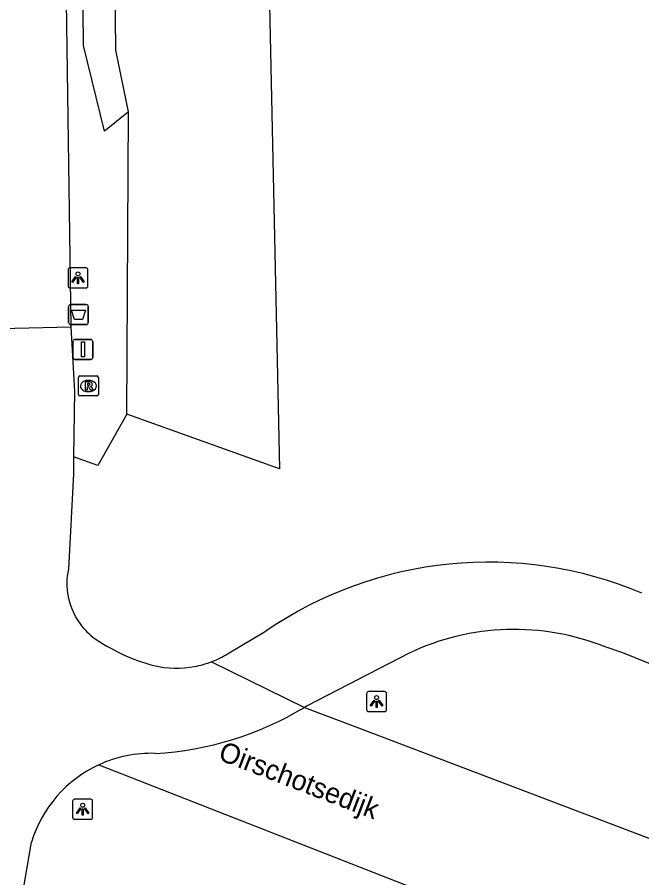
# Model space of a CAD drawing. Extents: x 155209 to 156823, y 385356 to 388482.
# Drawn here: x 155383.98 to 155415.19, y 386855.08 to 386898.09 of the extents above; entities that cross this region are included whole.
import ezdxf

# ---------------------------------------------------------------- set-up
doc = ezdxf.new("R2010")
doc.units = 0
for name, color, linetype in [('IMGEO_Afvalbak', 7, 'Continuous'), ('IMGEO_Fietspad_gesloten', 7, 'Continuous'), ('IMGEO_Groenvoorziening', 7, 'Continuous'), ('IMGEO_Lichtpunt', 7, 'Continuous'), ('IMGEO_Openbare_ruimte_label', 7, 'Continuous'), ('IMGEO_Rijbaan_lokaal_gesloten', 7, 'Continuous'), ('IMGEO_Rioolput', 7, 'Continuous'), ('IMGEO_Verkeersbordpaal', 7, 'Continuous'), ('IMGEO_Waterloop', 7, 'Continuous')]:
    doc.layers.add(name, color=color, linetype=linetype)

msp = doc.modelspace()

# ---------------------------------------------------------------- linework, layer by layer
at = {"layer": 'IMGEO_Afvalbak'}
for p, q in [((155386.544, 386882.829), (155386.544, 386883.629)), ((155386.544, 386883.629), (155386.544, 386882.829)), ((155386.644, 386883.729), (155387.434, 386883.729)), ((155387.434, 386883.729), (155386.644, 386883.729)), ((155387.534, 386883.629), (155387.534, 386882.829)), ((155387.534, 386882.829), (155387.534, 386883.629)), ((155387.434, 386882.729), (155386.644, 386882.729)), ((155386.644, 386882.729), (155387.434, 386882.729))]:
    msp.add_line(p, q, dxfattribs=at)
msp.add_lwpolyline([(155386.687, 386883.443), (155387.391, 386883.443), (155387.242, 386882.973), (155386.836, 386882.973), (155386.687, 386883.443)], dxfattribs=at)
for centre, start, end in [((155386.644, 386883.629), 90, 180), ((155386.644, 386883.629), 90, 180), ((155387.434, 386883.629), 0, 90), ((155387.434, 386883.629), 360, 90), ((155386.644, 386882.829), 180, 270), ((155386.644, 386882.829), 180, 270), ((155387.434, 386882.829), 270, 0), ((155387.434, 386882.829), 270, 0)]:
    msp.add_arc(centre, 0.1, start, end, dxfattribs=at)
at = {"layer": 'IMGEO_Fietspad_gesloten'}
for points in [[(155385.413, 386956.748), (155385.603, 386955.738), (155386.663, 386882.616)], [(155383.155, 386882.53), (155386.663, 386882.616)], [(155386.663, 386882.616), (155386.843, 386879.394), (155386.801, 386876.114)], [(155386.801, 386876.114), (155386.79, 386875.274), (155386.535, 386870.503)], [(155394.487, 386866.267), (155396.425, 386867.426)], [(155466.767, 386846.51), (155418.719, 386864.507), (155414.232, 386866.333), (155413.361, 386866.621)], [(155403.572, 386866.316), (155398.462, 386863.678), (155398.335, 386863.601)], [(155393.692, 386865.88), (155398.335, 386863.601)], [(155376.591, 386809.635), (155377.495, 386814.325), (155383.299, 386848.707), (155384.694, 386856.865)]]:
    msp.add_lwpolyline(points, dxfattribs=at)
for centre, radius, start, end in [((155389.897, 386869.798), 3.435, 168.1555, 213.8152), ((155407.522, 386851.188), 19.668, 67.0661, 124.3484), ((155389.896, 386869.791), 3.43, 213.7329, 231.3216), ((155408.816, 386855.242), 12.253, 68.2278, 115.3414), ((155393.271, 386874.947), 9.583, 234.8348, 255.1048), ((155391.895, 386870.581), 5.033, 290.917, 300.996), ((155391.901, 386870.624), 5.071, 280.6868, 290.6876), ((155391.932, 386870.508), 4.951, 256.8808, 280.5831), ((155390.673, 386855.055), 6.247, 114.7756, 163.16)]:
    msp.add_arc(centre, radius, start, end, dxfattribs=at)
at = {"layer": 'IMGEO_Groenvoorziening'}
for points in [[(155395.168, 386964.319), (155397.089, 386875.516), (155389.459, 386878.251)], [(155389.459, 386878.251), (155389.537, 386893.35)], [(155389.459, 386878.251), (155388.004, 386875.687), (155386.801, 386876.114)]]:
    msp.add_lwpolyline(points, dxfattribs=at)
at = {"layer": 'IMGEO_Lichtpunt'}
for p, q in [((155387.422, 386885.558), (155386.614, 386885.558)), ((155387.422, 386885.558), (155386.614, 386885.558)), ((155386.52, 386885.463), (155386.52, 386884.656)), ((155386.52, 386885.463), (155386.52, 386884.656)), ((155387.516, 386884.656), (155387.516, 386885.463)), ((155387.516, 386884.656), (155387.516, 386885.463)), ((155386.614, 386884.562), (155387.422, 386884.562)), ((155386.614, 386884.562), (155387.422, 386884.562)), ((155401.436, 386864.292), (155401.436, 386863.485)), ((155401.436, 386864.292), (155401.436, 386863.485)), ((155402.338, 386864.387), (155401.53, 386864.387)), ((155402.338, 386864.387), (155401.53, 386864.387)), ((155402.432, 386863.485), (155402.432, 386864.292)), ((155402.432, 386863.485), (155402.432, 386864.292)), ((155401.53, 386863.391), (155402.338, 386863.391)), ((155401.53, 386863.391), (155402.338, 386863.391)), ((155386.749, 386858.912), (155386.749, 386858.105)), ((155386.749, 386858.912), (155386.749, 386858.105)), ((155387.651, 386859.007), (155386.843, 386859.007)), ((155387.651, 386859.007), (155386.843, 386859.007)), ((155387.745, 386858.105), (155387.745, 386858.912)), ((155387.745, 386858.105), (155387.745, 386858.912)), ((155386.843, 386858.011), (155387.651, 386858.011)), ((155386.843, 386858.011), (155387.651, 386858.011))]:
    msp.add_line(p, q, dxfattribs=at)
for points in [[(155386.894, 386885.127), (155386.933, 386885.099), (155386.745, 386884.837), (155386.707, 386884.864), (155386.894, 386885.127)], [(155386.996, 386885.079), (155387.043, 386885.079), (155387.043, 386884.757), (155386.996, 386884.757), (155386.996, 386885.079)], [(155387.106, 386885.099), (155387.144, 386885.126), (155387.331, 386884.864), (155387.292, 386884.836), (155387.106, 386885.099)], [(155401.81, 386863.956), (155401.849, 386863.928), (155401.661, 386863.666), (155401.623, 386863.693), (155401.81, 386863.956)], [(155401.912, 386863.908), (155401.959, 386863.908), (155401.959, 386863.586), (155401.912, 386863.586), (155401.912, 386863.908)], [(155402.022, 386863.928), (155402.06, 386863.955), (155402.247, 386863.693), (155402.208, 386863.665), (155402.022, 386863.928)], [(155387.123, 386858.576), (155387.162, 386858.548), (155386.974, 386858.286), (155386.936, 386858.313), (155387.123, 386858.576)], [(155387.225, 386858.528), (155387.272, 386858.528), (155387.272, 386858.206), (155387.225, 386858.206), (155387.225, 386858.528)], [(155387.335, 386858.548), (155387.373, 386858.575), (155387.56, 386858.313), (155387.521, 386858.285), (155387.335, 386858.548)]]:
    msp.add_lwpolyline(points, dxfattribs=at)
for centre in [(155387.019, 386885.261), (155401.935, 386864.09), (155387.248, 386858.71)]:
    msp.add_circle(centre, 0.0994, dxfattribs=at)
for centre, start, end in [((155386.614, 386885.463), 90, 180), ((155386.614, 386885.463), 90, 180), ((155387.422, 386885.463), 0, 90), ((155387.422, 386885.463), 0, 90), ((155386.614, 386884.656), 180, 270), ((155386.614, 386884.656), 180, 270), ((155387.422, 386884.656), 270, 0), ((155387.422, 386884.656), 270, 360), ((155401.53, 386864.292), 90, 180), ((155401.53, 386864.292), 90, 180), ((155402.338, 386864.292), 0, 90), ((155402.338, 386864.292), 0, 90), ((155401.53, 386863.485), 180, 270), ((155401.53, 386863.485), 180, 270), ((155402.338, 386863.485), 270, 0), ((155402.338, 386863.485), 270, 360), ((155386.843, 386858.912), 90, 180), ((155386.843, 386858.912), 90, 180), ((155387.651, 386858.912), 0, 90), ((155387.651, 386858.912), 0, 90), ((155386.843, 386858.105), 180, 270), ((155386.843, 386858.105), 180, 270), ((155387.651, 386858.105), 270, 0), ((155387.651, 386858.105), 270, 360)]:
    msp.add_arc(centre, 0.0946, start, end, dxfattribs=at)
at = {"layer": 'IMGEO_Rijbaan_lokaal_gesloten'}
for points in [[(155398.335, 386863.601), (155400.892, 386862.631), (155414.712, 386857.387), (155445.113, 386845.774), (155457.912, 386840.913)], [(155388.055, 386860.727), (155422.593, 386847.21), (155447.01, 386837.973), (155453.658, 386835.338), (155457.34, 386833.958)]]:
    msp.add_lwpolyline(points, dxfattribs=at)
for centre, radius, start, end in [((155389.954, 386877.519), 16.247, 273.2741, 301.0545), ((155390.677, 386855.042), 6.261, 88.1205, 114.7565)]:
    msp.add_arc(centre, radius, start, end, dxfattribs=at)
at = {"layer": 'IMGEO_Rioolput'}
for p, q in [((155387.038, 386879.235), (155387.038, 386880.087)), ((155387.113, 386880.161), (155387.965, 386880.161)), ((155387.526, 386879.941), (155387.551, 386879.941)), ((155388.039, 386880.087), (155388.039, 386879.235)), ((155387.965, 386879.161), (155387.113, 386879.161)), ((155387.549, 386879.381), (155387.524, 386879.381))]:
    msp.add_line(p, q, dxfattribs=at)
for points in [[(155387.038, 386879.235), (155387.038, 386880.087)], [(155387.113, 386880.161), (155387.965, 386880.161)], [(155388.039, 386880.087), (155388.039, 386879.235)], [(155387.627, 386879.859), (155387.375, 386879.861), (155387.375, 386879.461)], [(155387.375, 386879.461), (155387.499, 386879.461), (155387.499, 386879.623), (155387.51, 386879.623)], [(155387.553, 386879.78), (155387.499, 386879.78), (155387.499, 386879.699)], [(155387.499, 386879.699), (155387.551, 386879.699)], [(155387.557, 386879.594), (155387.628, 386879.461), (155387.768, 386879.461), (155387.703, 386879.587)], [(155387.965, 386879.161), (155387.113, 386879.161)]]:
    msp.add_lwpolyline(points, dxfattribs=at)
for centre, radius, start, end in [((155387.115, 386880.085), 0.0765, 91.552, 178.448), ((155387.115, 386880.085), 0.0765, 91.552, 178.448), ((155387.963, 386880.085), 0.0765, 1.552, 88.448), ((155387.963, 386880.085), 0.0765, 1.552, 88.448), ((155387.509, 386879.57), 0.0533, 26.0293, 88.6989), ((155387.535, 386879.888), 0.19, 274.7715, 282.9687), ((155387.559, 386879.684), 0.0964, 77.0061, 93.1865), ((155387.573, 386879.741), 0.0378, 276.6634, 79.6772), ((155387.626, 386879.749), 0.109, 350.3612, 89.416), ((155387.624, 386879.749), 0.112, 277.5842, 350.9817), ((155387.608, 386879.534), 0.108, 29.5134, 73.7905), ((155387.115, 386879.237), 0.0765, 181.552, 268.448), ((155387.115, 386879.237), 0.0765, 181.552, 268.448), ((155387.963, 386879.237), 0.0765, 271.552, 358.448), ((155387.963, 386879.237), 0.0765, 271.552, 358.448)]:
    msp.add_arc(centre, radius, start, end, dxfattribs=at)
for centre, major_axis, ratio, start_param, end_param in [((155387.525, 386879.661), (-0.387, 0.002), 0.722429, 4.712389, 7.853982), ((155387.55, 386879.661), (-0.39, 0.002), 0.717154, 1.570796, 4.712389)]:
    msp.add_ellipse(centre, major_axis=major_axis, ratio=ratio, start_param=start_param, end_param=end_param, dxfattribs=at)
at = {"layer": 'IMGEO_Verkeersbordpaal'}
for p, q in [((155386.768, 386881.083), (155386.768, 386881.883)), ((155386.768, 386881.883), (155386.768, 386881.083)), ((155386.868, 386881.983), (155387.658, 386881.983)), ((155387.658, 386881.983), (155386.868, 386881.983)), ((155387.758, 386881.883), (155387.758, 386881.083)), ((155387.758, 386881.083), (155387.758, 386881.883)), ((155387.658, 386880.983), (155386.868, 386880.983)), ((155386.868, 386880.983), (155387.658, 386880.983))]:
    msp.add_line(p, q, dxfattribs=at)
msp.add_lwpolyline([(155387.188, 386881.858), (155387.338, 386881.858), (155387.338, 386881.108), (155387.188, 386881.108), (155387.188, 386881.858)], dxfattribs=at)
for centre, start, end in [((155386.868, 386881.883), 90, 180), ((155386.868, 386881.883), 90, 180), ((155387.658, 386881.883), 0, 90), ((155387.658, 386881.883), 360, 90), ((155386.868, 386881.083), 180, 270), ((155386.868, 386881.083), 180, 270), ((155387.658, 386881.083), 270, 0), ((155387.658, 386881.083), 270, 0)]:
    msp.add_arc(centre, 0.1, start, end, dxfattribs=at)
at = {"layer": 'IMGEO_Waterloop'}
for points in [[(155389.537, 386893.35), (155388.915, 386896.442), (155388.32, 386952.733)], [(155389.537, 386893.35), (155388.34, 386892.391), (155387.298, 386896.672), (155386.781, 386950.846)]]:
    msp.add_lwpolyline(points, dxfattribs=at)

# ---------------------------------------------------------------- texts
at = {"layer": 'IMGEO_Openbare_ruimte_label'}
msp.add_text('Oirschotsedijk', height=1, rotation=339.0283, dxfattribs=at).set_placement((155393.971, 386861.002))

doc.saveas('drawing.dxf')
